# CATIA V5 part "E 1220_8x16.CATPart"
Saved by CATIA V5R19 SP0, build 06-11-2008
Nomenclature: E 1220_8x16
Description: PART-E 1220_8x16-DESC
Property "Hersteller": "Meusburger"
Property "Material": "10.9 DIN 7991"
Property "Bestellnummer": "E 1220/8x16"
Property "Teilenummer": "E 1220/8x16"
Property "Beschreibung": "Senkkopfschraube mit Innensechskant _ Countersunk head screw with hexagon socket"
Material "Steel": density 7860 kg/m3, Young's modulus 2e+11 Pa, Poisson ratio 0.266, thermal expansion 1.17e-05 1/K
Bounding box of the stored display mesh (mm): x -8 to 8, y -8 to 8, z -4.4 to 11.6
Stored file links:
  G:\UTB\Kombinované\Bakalářská práce\Catia\FORMA\E 1220_8x16.CATPart
  D:\Aplikace\CATIA\Nová složka\win_b64\startup\materials\Catalog.CATMaterial
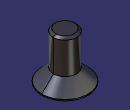
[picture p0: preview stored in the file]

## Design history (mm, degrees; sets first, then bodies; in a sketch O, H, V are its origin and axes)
Body1 "E 1220_8x16" (main body)
  Solid1: solid without history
